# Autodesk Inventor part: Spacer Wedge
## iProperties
Created: 2006-12
Part Number: Spacer Wedge
Document SubType Name: Modeling
Designer: Administrator
Density: 1 g/cm^3
Author: Administrator
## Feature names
1. Extrusion1
2. Extrusion2
3. Extrusion3
4. Hole1
5. Hole2
